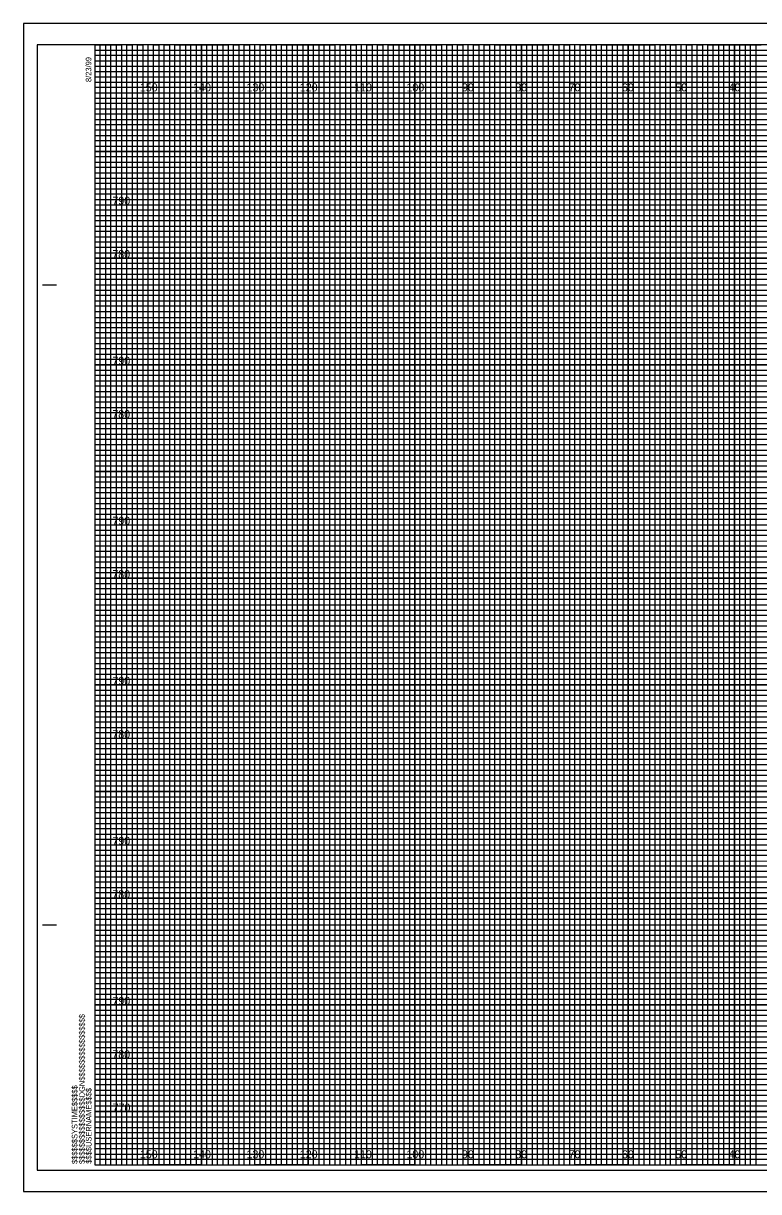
# Model space of a CAD drawing. Extents: x -13 to 323, y 875 to 1094.
# Drawn here: x -13.4 to 124.5, y 875 to 1094 of the extents above; entities that cross this region are included whole.
import ezdxf

# ---------------------------------------------------------------- set-up
doc = ezdxf.new("R2010")
doc.units = 0
for name, color, linetype in [('Prop XS Elevation Labels', 7, 'Continuous'), ('Prop XS Offset Labels', 7, 'Continuous'), ('Sheet Cross Section CELL', 7, 'Continuous'), ('Sheet Cross Section Grid Major CELL', 7, 'Continuous'), ('Sheet Cross Section Grid Middle CELL', 7, 'Continuous'), ('Sheet Cross Section Grid Minor 1 CELL', 7, 'Continuous'), ('Sheet Cross Section Grid Minor 2 CELL', 7, 'Continuous'), ('Sheet Cutting Line CELL', 7, 'Continuous'), ('Sheet DOT Grid CELL', 7, 'Continuous'), ('Sheet Plot Border Inside CELL', 7, 'Continuous'), ('Sheet Plot Border Outside CELL', 7, 'Continuous')]:
    doc.layers.add(name, color=color, linetype=linetype)

msp = doc.modelspace()

# ---------------------------------------------------------------- linework, layer by layer
at = {"layer": 'Sheet Cross Section CELL'}
for p, q in [((-9.8, 1045), (-7.3, 1045)), ((-9.7, 1045), (-7.2, 1045)), ((-9.8, 925), (-7.3, 925)), ((-9.7, 925), (-7.2, 925)), ((0, 880), (0, 880)), ((0, 880), (0, 880)), ((0, 880), (0, 880)), ((0, 880), (0, 880)), ((0, 880), (0, 880)), ((0, 880), (0, 880)), ((0, 880), (0, 880))]:
    msp.add_line(p, q, dxfattribs=at)
msp.add_lwpolyline([(320, 1090), (0, 1090), (0, 880), (320, 880)], close=True, dxfattribs=at)
at = {"layer": 'Sheet Cross Section Grid Major CELL'}
for p, q in [((10, 1090), (0, 1090)), ((10, 880), (10, 1090)), ((30, 1090), (20, 1090)), ((20, 1090), (20, 880)), ((30, 880), (30, 1090)), ((50, 1090), (40, 1090)), ((40, 1090), (40, 880)), ((50, 880), (50, 1090)), ((70, 1090), (60, 1090)), ((60, 1090), (60, 880)), ((70, 880), (70, 1090)), ((90, 1090), (80, 1090)), ((80, 1090), (80, 880)), ((90, 880), (90, 1090)), ((110, 1090), (100, 1090)), ((100, 1090), (100, 880)), ((110, 880), (110, 1090)), ((130, 1090), (120, 1090)), ((120, 1090), (120, 880)), ((20, 880), (10, 880)), ((40, 880), (30, 880)), ((60, 880), (50, 880)), ((80, 880), (70, 880)), ((100, 880), (90, 880)), ((120, 880), (110, 880))]:
    msp.add_line(p, q, dxfattribs=at)
for points in [[(0, 1080), (320, 1080), (320, 1070), (0, 1070)], [(0, 1060), (320, 1060), (320, 1050), (0, 1050)], [(0, 1040), (320, 1040), (320, 1030), (0, 1030)], [(0, 1020), (320, 1020), (320, 1010), (0, 1010)], [(0, 1000), (320, 1000), (320, 990), (0, 990)], [(0, 980), (320, 980), (320, 970), (0, 970)], [(0, 960), (320, 960), (320, 950), (0, 950)], [(0, 940), (320, 940), (320, 930), (0, 930)], [(0, 920), (320, 920), (320, 910), (0, 910)], [(0, 900), (320, 900), (320, 890), (0, 890)]]:
    msp.add_lwpolyline(points, dxfattribs=at)
at = {"layer": 'Sheet Cross Section Grid Middle CELL'}
for points in [[(0, 1090), (5, 1090), (5, 880), (15, 880), (15, 1090), (25, 1090), (25, 880), (35, 880), (35, 1090), (45, 1090), (45, 880), (55, 880), (55, 1090), (65, 1090), (65, 880), (75, 880), (75, 1090), (85, 1090), (85, 880), (95, 880), (95, 1090), (105, 1090), (105, 880), (115, 880), (115, 1090), (125, 1090)], [(0, 1085), (275, 1085)], [(0, 1065), (320, 1065), (320, 1075), (0, 1075)], [(0, 1045), (320, 1045), (320, 1055), (0, 1055)], [(0, 1025), (320, 1025), (320, 1035), (0, 1035)], [(0, 1005), (320, 1005), (320, 1015), (0, 1015)], [(0, 985), (320, 985), (320, 995), (0, 995)], [(0, 965), (320, 965), (320, 975), (0, 975)], [(0, 945), (320, 945), (320, 955), (0, 955)], [(0, 925), (320, 925), (320, 935), (0, 935)], [(0, 905), (320, 905), (320, 915), (0, 915)], [(0, 885), (320, 885), (320, 895), (0, 895)]]:
    msp.add_lwpolyline(points, dxfattribs=at)
at = {"layer": 'Sheet Cross Section Grid Minor 1 CELL'}
for p, q in [((0, 1089), (260, 1089)), ((260, 1087.98), (0, 1087.98)), ((0, 1087.98), (0, 1087)), ((0, 1087), (260, 1087)), ((260, 1085.89), (0, 1085.89)), ((0, 1085.89), (0, 1084)), ((0, 1084), (320, 1084))]:
    msp.add_line(p, q, dxfattribs=at)
for points in [[(0, 1083), (270, 1083), (320, 1083), (320, 1082), (0, 1082)], [(0, 1081), (320, 1081), (320, 1079), (0, 1079)], [(0, 1078), (320, 1078), (320, 1077), (0, 1076.98)], [(0, 1076), (320, 1076), (320, 1074), (0, 1074)], [(0, 1073), (320, 1073), (320, 1072), (0, 1072)], [(0, 1071), (320, 1071), (320, 1069), (0, 1069)], [(0, 1068), (320, 1068), (320, 1067), (0, 1067)], [(0, 1066), (320, 1066), (320, 1064), (0, 1064)], [(0, 1063), (320, 1063), (320, 1062), (0, 1062)], [(0, 1061), (320, 1061), (320, 1059), (0, 1059)], [(0, 1058), (320, 1058), (320, 1057), (0, 1057)], [(0, 1056), (320, 1056), (320, 1053.95), (320, 1053), (320, 1052), (0, 1052)], [(0, 1054), (320, 1054), (320, 1053), (0, 1053)], [(0, 1051), (320, 1051), (320, 1049), (0, 1049.03)], [(0, 1049.03), (320, 1049), (320, 1048), (0, 1048)], [(0, 1047), (320, 1047), (320, 1046), (0, 1046)], [(0, 1044), (320, 1044), (320, 1043), (0, 1043)], [(0, 1042), (320, 1042), (320, 1041), (0, 1041)], [(-0.07, 1038.89), (320, 1038.89), (320, 1037.88), (-0.07, 1037.88)], [(0, 1037), (320, 1037), (320, 1036), (0, 1036)], [(0, 1034), (320, 1034), (320, 1033), (0, 1033)], [(0, 1032), (320, 1032), (320, 1031), (0, 1031)], [(0, 1029), (320, 1029), (320, 1028), (0, 1028)], [(0, 1027), (320, 1027), (320, 1026), (0, 1026)], [(0, 1024), (320, 1024), (320, 1023), (0, 1023)], [(0, 1022), (320, 1022), (320, 1021), (0, 1021)], [(0, 1019), (320, 1019), (319.99, 1017.98), (0, 1018)], [(0, 1017), (320, 1017), (320, 1016), (0, 1016)], [(0, 1014), (320, 1014), (320, 1013), (0, 1013)], [(0, 1012), (320, 1012), (320, 1011), (0, 1011)], [(0, 1009), (320, 1009), (320, 1008), (0, 1008)], [(0, 1007), (320, 1007), (320, 1006), (0, 1006)], [(0, 1004), (320, 1004), (320, 1003), (0, 1003)], [(0, 1002), (320, 1002), (320, 1001), (0, 1001)], [(0, 999), (320, 999), (320, 998), (0, 998)], [(0, 996.99), (320.07, 996.91), (320, 996), (0, 996)], [(0, 994), (320, 994), (320, 993), (0, 993)], [(0, 992), (320, 992), (320, 991), (0, 991)], [(0, 989), (320, 989), (320, 988), (0, 988)], [(0, 987), (320, 987), (320, 986), (0, 986)], [(0, 984), (320, 984), (320, 983), (0, 983)], [(0, 982), (320, 982), (320, 981), (0, 981)], [(0, 979), (320, 979), (320, 978), (0, 978)], [(0, 977), (320, 977), (320, 976), (0, 976)], [(0, 974), (320, 974), (320, 973), (0, 973)], [(0, 972), (320, 972), (320, 971), (0, 971)], [(0, 969), (320, 969), (320, 968), (0, 968)], [(0, 967), (320, 967), (320, 966), (0, 966)], [(0, 964), (320, 964), (320, 963), (0, 963)], [(0, 962), (320, 962), (320, 961), (0, 961)], [(0, 959), (320, 959), (319.99, 957.98), (0, 958)], [(0, 957), (320, 957), (320, 956), (0, 956)], [(0, 954), (320, 954), (320, 953), (0, 953)], [(0, 952), (320, 952), (320, 951), (0, 951)], [(0, 949), (320, 949), (320, 948), (0, 948)], [(0, 947), (320, 947), (320, 946), (0, 946)], [(0, 944), (320, 944), (320, 943), (0, 943)], [(0, 942), (320, 942), (320, 941), (0, 941)], [(0, 939), (320, 939), (320, 938), (0, 938)], [(0, 936.99), (320.07, 936.91), (320, 936), (0, 936)], [(0, 934), (320, 934), (320, 933), (0, 933)], [(0, 932), (320, 932), (320, 931), (0, 931)], [(0, 929), (320, 929), (320, 928), (0, 928)], [(0, 927), (320, 927), (320, 926), (0, 926)], [(0, 924), (320, 924), (320, 923), (0, 923)], [(0, 922), (320, 922), (320, 921), (0, 921)], [(0, 919), (320, 919), (320, 918), (0, 918)], [(0, 917), (320, 917), (320, 916), (0, 916)], [(0, 914), (320, 914), (320, 913), (0, 913)], [(0, 912), (320, 912), (320, 911), (0, 911)], [(0, 909), (320, 909), (320, 908), (0, 908)], [(0, 907), (320, 907), (320, 906), (0, 906)], [(0, 904), (320, 904), (320, 903), (0, 903)], [(0, 902), (320, 902), (320, 901), (0, 901)], [(0, 899), (320, 899), (320, 898), (0, 898)], [(0, 897), (320, 897), (320, 896), (0, 896)], [(0, 894), (320, 894), (320, 893), (0, 893)], [(0, 892), (320, 892), (320, 891), (0, 891)], [(0, 889), (320, 889), (320, 888), (0, 888)], [(0, 887), (320, 887), (320, 886), (0, 886)], [(0, 884), (320, 884), (320, 883), (0, 883)], [(0, 882), (320, 882), (320, 881), (0, 881)]]:
    msp.add_lwpolyline(points, dxfattribs=at)
at = {"layer": 'Sheet Cross Section Grid Minor 2 CELL'}
for points in [[(0, 880), (1, 880), (1, 1090), (2, 1090), (2, 880)], [(2, 880), (3, 880), (3, 1090), (4, 1090), (4, 880)], [(5, 880), (6, 880), (6, 1090), (7, 1090), (7, 880)], [(7, 880), (8, 880), (8, 1090), (9, 1090), (9, 880)], [(10, 880), (11, 880), (11, 1090), (12, 1090), (12, 880)], [(12, 880), (13, 880), (13, 1090), (14, 1090), (14, 880)], [(15, 880), (16, 880), (16, 1090), (17, 1090), (17, 880)], [(17, 880), (18, 880), (18, 1090), (19, 1090), (19, 880)], [(20, 880), (21, 880), (21, 1090), (22, 1090), (22, 880)], [(22, 880), (23, 880), (23, 1090), (24, 1090), (24, 880)], [(25, 880), (26, 880), (26, 1090), (27, 1090), (27, 880)], [(27, 880), (28, 880), (28, 1090), (29, 1090), (29, 880)], [(30, 880), (31, 880), (31, 1090), (32, 1090), (32, 880)], [(32, 880), (33, 880), (33, 1090), (34, 1090), (34, 880)], [(35, 880), (36, 880), (36, 1090), (37, 1090), (37, 880)], [(37, 880), (38, 880), (38, 1090), (39, 1090), (39, 880)], [(40, 880), (41, 880), (41, 1090), (42, 1090), (42, 880)], [(42, 880), (43, 880), (43, 1090), (44, 1090), (44, 880)], [(45, 880), (46, 880), (46, 1090), (47, 1090), (47, 880)], [(47, 880), (48, 880), (48, 1090), (49, 1090), (49, 880)], [(50, 880), (51, 880), (51, 1090), (52, 1090), (52, 880)], [(52, 880), (53, 880), (53, 1090), (54, 1090), (54, 880)], [(55, 880), (56, 880), (56, 1090), (57, 1090), (57, 880)], [(57, 880), (58, 880), (58, 1090), (59, 1090), (59, 880)], [(60, 880), (61, 880), (61, 1090), (62, 1090), (62, 880)], [(62, 880), (63, 880), (63, 1090), (64, 1090), (64, 880)], [(65, 880), (66, 880), (66, 1090), (67, 1090), (67, 880)], [(67, 880), (68, 880), (68, 1090), (69, 1090), (69, 880)], [(70, 880), (71, 880), (71, 1090), (72, 1090), (72, 880)], [(72, 880), (73, 880), (73, 1090), (74, 1090), (74, 880)], [(75, 880), (76, 880), (76, 1090), (77, 1090), (77, 880)], [(77, 880), (78, 880), (78, 1090), (79, 1090), (79, 880)], [(80, 880), (81, 880), (81, 1090), (82, 1090), (82, 880)], [(82, 880), (83, 880), (83, 1090), (84, 1090), (84, 880)], [(85, 880), (86, 880), (86, 1090), (87, 1090), (87, 880)], [(87, 880), (88, 880), (88, 1090), (89, 1090), (89, 880)], [(90, 880), (91, 880), (91, 1090), (92, 1090), (92, 880)], [(92, 880), (93, 880), (93, 1090), (94, 1090), (94, 880)], [(95, 880), (96, 880), (96, 1090), (97, 1090), (97, 880)], [(97, 880), (98, 880), (98, 1090), (99, 1090), (99, 880)], [(100, 880), (101, 880), (101, 1090), (102, 1090), (102, 880)], [(102, 880), (103, 880), (103, 1090), (104, 1090), (104, 880)], [(105, 880), (106, 880), (106, 1090), (107, 1090), (107, 880)], [(107, 880), (108, 880), (108, 1090), (109, 1090), (109, 880)], [(110, 880), (111, 880), (111, 1090), (112, 1090), (112, 880)], [(112, 880), (113, 880), (113, 1090), (114, 1090), (114, 880)], [(115, 880), (116, 880), (116, 1090), (117, 1090), (117, 880)], [(117, 880), (118, 880), (118, 1090), (119, 1090), (119, 880)], [(120, 880), (121, 880), (121, 1090), (122, 1090), (122, 880)], [(122, 880), (123, 880), (123, 1090), (124, 1090), (124, 880)]]:
    msp.add_lwpolyline(points, dxfattribs=at)
at = {"layer": 'Sheet Cutting Line CELL'}
for p, q in [((323.3, 1094), (-13.4, 1094)), ((-13.4, 1094), (-13.4, 875)), ((-13.4, 875), (323.3, 875))]:
    msp.add_line(p, q, dxfattribs=at)
at = {"layer": 'Sheet DOT Grid CELL'}
for p, q in [((10, 880), (10, 1090)), ((20, 880), (20, 1090)), ((30, 880), (30, 1090)), ((40, 880), (40, 1090)), ((50, 880), (50, 1090)), ((60, 880), (60, 1090)), ((70, 880), (70, 1090)), ((80, 880), (80, 1090)), ((90, 880), (90, 1090)), ((100, 880), (100, 1090)), ((110, 880), (110, 1090)), ((120, 880), (120, 1090)), ((0, 1080), (320, 1080)), ((0, 1070), (320, 1070)), ((0, 1060), (320, 1060)), ((0, 1050), (320, 1050)), ((0, 1040), (320, 1040)), ((0, 1030), (320, 1030)), ((0, 1020), (320, 1020)), ((0, 1010), (320, 1010)), ((0, 1000), (320, 1000)), ((0, 990), (320, 990)), ((0, 980), (320, 980)), ((0, 970), (320, 970)), ((0, 960), (320, 960)), ((0, 950), (320, 950)), ((0, 940), (320, 940)), ((0, 930), (320, 930)), ((0, 920), (320, 920)), ((0, 910), (320, 910)), ((0, 900), (320, 900)), ((0, 890), (320, 890))]:
    msp.add_line(p, q, dxfattribs=at)
at = {"layer": 'Sheet Plot Border Inside CELL'}
msp.add_lwpolyline([(-10.8, 879), (322.4, 879), (322.4, 1090), (-10.8, 1090)], close=True, dxfattribs=at)
at = {"layer": 'Sheet Plot Border Outside CELL'}
msp.add_lwpolyline([(-13.4, 875), (323.3, 875), (323.3, 1094), (-13.4, 1094)], close=True, dxfattribs=at)

# ---------------------------------------------------------------- texts
at = {"layer": 'Prop XS Elevation Labels'}
for s, p in [('790', (3.3, 1060)), ('780', (3.28, 1050)), ('790', (3.3, 1030)), ('780', (3.28, 1020)), ('790', (3.3, 1000)), ('780', (3.28, 990)), ('790', (3.3, 970)), ('780', (3.28, 960)), ('790', (3.3, 940)), ('780', (3.28, 930)), ('790', (3.3, 910)), ('780', (3.28, 900)), ('770', (3.33, 890))]:
    msp.add_text(s, height=1.5, dxfattribs=at).set_placement(p)
at = {"layer": 'Prop XS Offset Labels'}
for s, p in [('150', (8.44, 1081.25)), ('140', (18.44, 1081.25)), ('130', (28.44, 1081.25)), ('120', (38.44, 1081.25)), ('110', (48.62, 1081.25)), ('100', (58.44, 1081.25)), ('90', (68.86, 1081.25)), ('80', (78.86, 1081.25)), ('70', (88.86, 1081.25)), ('60', (98.86, 1081.25)), ('50', (108.86, 1081.25)), ('40', (118.86, 1081.25)), ('150', (8.44, 881.25)), ('140', (18.44, 881.25)), ('130', (28.44, 881.25)), ('120', (38.44, 881.25)), ('110', (48.62, 881.25)), ('100', (58.44, 881.25)), ('90', (68.86, 881.25)), ('80', (78.86, 881.25)), ('70', (88.86, 881.25)), ('60', (98.86, 881.25)), ('50', (108.86, 881.25)), ('40', (118.86, 881.25))]:
    msp.add_text(s, height=1.5, dxfattribs=at).set_placement(p)
at = {"layer": 'Sheet Cross Section CELL'}
for s, p in [('8/23/99', (-0.65, 1083)), ('$$$$$$$$$$$$$$$$DGN$$$$$$$$$$$$$$$$', (-1.88, 880.18)), ('$$$$$$SYSTIME$$$$$', (-3.26, 880.18)), ('$$$$USERNAME$$$$', (-0.62, 880.23))]:
    msp.add_text(s, height=1.05, rotation=90, dxfattribs=at).set_placement(p)

doc.saveas('drawing.dxf')
